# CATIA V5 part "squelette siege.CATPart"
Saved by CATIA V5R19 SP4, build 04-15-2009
Part number: squelette siege
Bounding box of the stored display mesh (mm): x -250 to 250, y 1050 to 1050, z 400 to 400
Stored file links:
  G:\EU_thinkMotion\CFAO_2010\MMS_groupe1\MMS_groupe1\OK\rragonneau\rragonneau\squelette siege.CATPart
  D:\Documents\Scolaire\MM2\CFAO\Brevet\MODELE CATIA\Squelette\Deambulateur.CATProduct
  G:\EU_thinkMotion\CFAO_2010\MMS_groupe1\MMS_groupe1\OK\rragonneau\rragonneau\Montants.CATPart
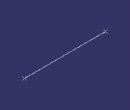
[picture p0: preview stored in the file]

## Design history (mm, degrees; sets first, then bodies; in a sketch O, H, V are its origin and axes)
Set1
  Line1: type PtPt, FirstPoint Point1, SecondPoint Point2
Set2
  Point1: linked copy from another document
  Point2: linked copy from another document
Body1 (main body)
